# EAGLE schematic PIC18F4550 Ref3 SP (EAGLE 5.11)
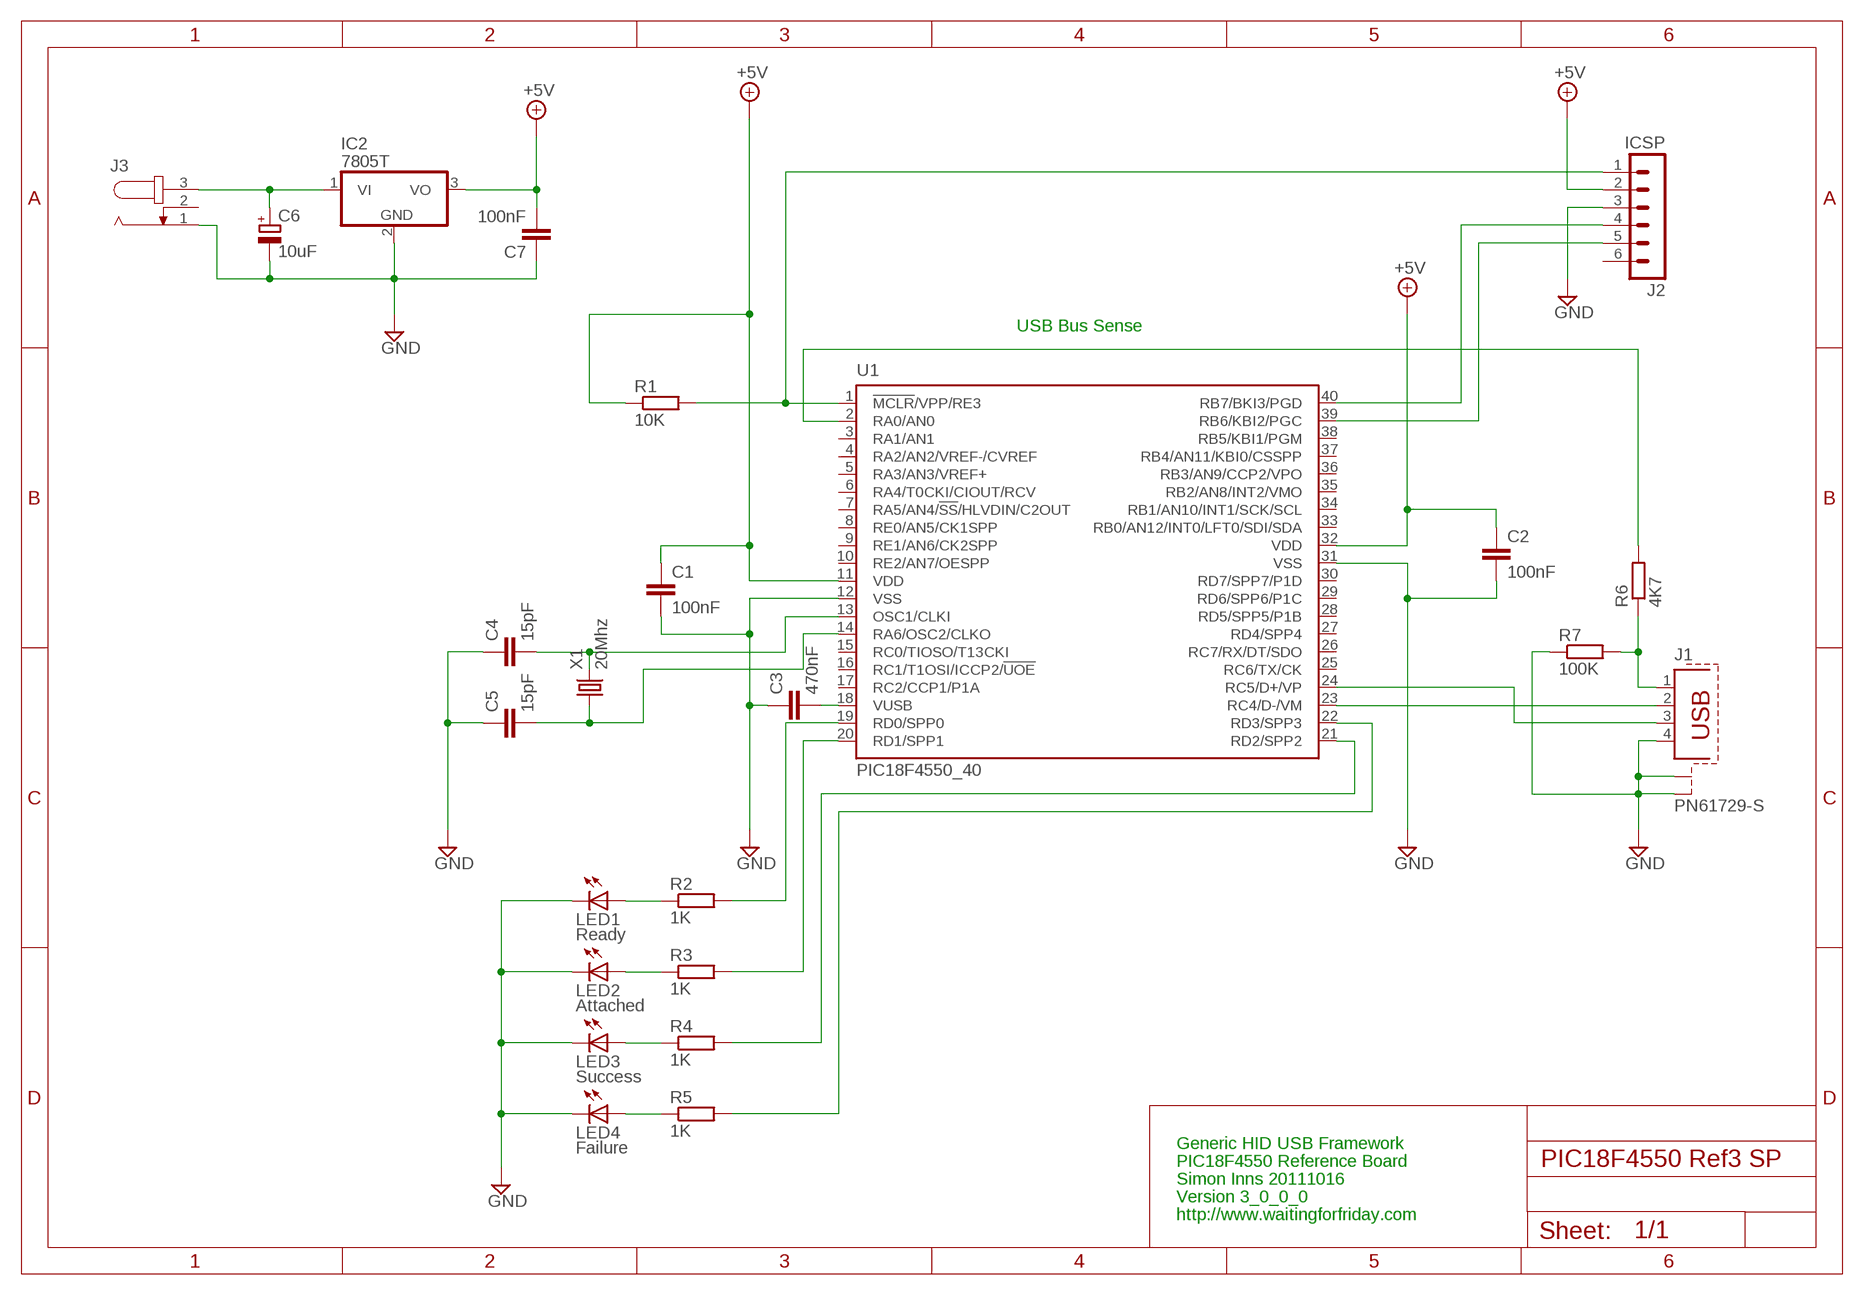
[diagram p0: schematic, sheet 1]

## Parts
C1  100nF  C-EU075-032X103  [C075-032X103]
C2  100nF  C-EU075-032X103  [C075-032X103]
C3  470nF  C-EU050-045X075  [C050-045X075]
C4  15pF  C-EU050-024X044  [C050-024X044]
C5  15pF  C-EU050-024X044  [C050-024X044]
C6  10uF  CPOL-EUE2.5-5  [E2,5-5]
C7  100nF  C-EU075-032X103  [C075-032X103]
IC2  7805T  [TO220H]
J1  PN61729-S  [PN61729-S]
J2  ICSP  MA06-1  [MA06-1]
J3  JACK-PLUG0  [SPC4077]
LED1  Ready  LED3MM  [LED3MM]
LED2  Attached  LED3MM  [LED3MM]
LED3  Success  LED3MM  [LED3MM]
LED4  Failure  LED3MM  [LED3MM]
R1  10K  R-EU_0207/10  [0207/10]
R2  1K  R-EU_0207/10  [0207/10]
R3  1K  R-EU_0207/10  [0207/10]
R4  1K  R-EU_0207/10  [0207/10]
R5  1K  R-EU_0207/10  [0207/10]
R6  4K7  R-EU_0207/10  [0207/10]
R7  100K  R-EU_0207/10  [0207/10]
U1  PIC18F4550_40  [DIL40]
X1  20Mhz  CRYSTALHC49U-V  [HC49U-V]

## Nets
+5V: C1.1 C2.1 C7.2 IC2.3(VO) J2.2 R1.1 U1.11(VDD) U1.32(VDD)
GND: C1.2 C2.2 C3.1 C4.1 C5.1 C6.- C7.1 IC2.2(GND) J1.4 J1.S1 J1.S2 J2.3 J3.1 LED1.K(C) LED2.K(C) LED3.K(C) LED4.K(C) R7.1 U1.12(VSS) U1.31(VSS)
N$1: J2.1 R1.2 U1.1(!MCLR!/VPP/RE3)
N$2: LED1.A R2.1
N$3: LED2.A R3.1
N$4: LED3.A R4.1
N$5: LED4.A R5.1
N$6: C4.2 U1.13(OSC1/CLKI) X1.2
N$7: C5.2 U1.14(RA6/OSC2/CLKO) X1.1
N$8: R2.2 U1.19(RD0/SPP0)
N$9: J2.4 U1.40(RB7/BKI3/PGD)
N$10: J2.5 U1.39(RB6/KBI2/PGC)
N$11: C3.2 U1.18(VUSB)
N$12: J1.2 U1.23(RC4/D-/VM)
N$13: J1.3 U1.24(RC5/D+/VP)
N$14: R3.2 U1.20(RD1/SPP1)
N$15: R4.2 U1.21(RD2/SPP2)
N$16: R5.2 U1.22(RD3/SPP3)
N$17: C6.+ IC2.1(VI) J3.3
N$18: J1.1 R6.1 R7.2
N$20: R6.2 U1.2(RA0/AN0)
Unconnected: J2.6 J3.2 U1.3(RA1/AN1) U1.4(RA2/AN2/VREF-/CVREF) U1.5(RA3/AN3/VREF+) U1.6(RA4/T0CKI/CIOUT/RCV) U1.7(RA5/AN4/!SS!/HLVDIN/C2OUT) U1.8(RE0/AN5/CK1SPP) U1.9(RE1/AN6/CK2SPP) U1.10(RE2/AN7/OESPP) U1.15(RC0/TIOSO/T13CKI) U1.16(RC1/T1OSI/ICCP2/!UOE) U1.17(RC2/CCP1/P1A) U1.25(RC6/TX/CK) U1.26(RC7/RX/DT/SDO) U1.27(RD4/SPP4) U1.28(RD5/SPP5/P1B) U1.29(RD6/SPP6/P1C) U1.30(RD7/SPP7/P1D) U1.33(RB0/AN12/INT0/LFT0/SDI/SDA) U1.34(RB1/AN10/INT1/SCK/SCL) U1.35(RB2/AN8/INT2/VMO) U1.36(RB3/AN9/CCP2/VPO) U1.37(RB4/AN11/KBI0/CSSPP) U1.38(RB5/KBI1/PGM)

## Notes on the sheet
- USB Bus Sense
- Generic HID USB Framework
- PIC18F4550 Reference Board
- Simon Inns 20111016
- Version 3_0_0_0
- http://www.waitingforfriday.com

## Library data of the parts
C1-C5 C7 = rcl:C-EU: CAPACITOR, European symbol
C6 = rcl:CPOL-EU: POLARIZED CAPACITOR, European symbol
IC2 = linear:78*: Positive VOLTAGE REGULATOR Source: http://cache.national.com/ds/LM/LM78L05.pdf http://www.fairchildsemi.com/ds/LM/LM7805.pdf
J1 = con-berg:PN61729-S: BERG USB connector; OC_FARNELL: unknown; OC_NEWARK: unknown
J2 = con-lstb:MA06-1: PIN HEADER; OC_FARNELL: unknown; OC_NEWARK: unknown
J3 = con-jack:JACK-PLUG: DC POWER JACK Power Jack, DC, Right Angle, Through Hole, Rated 5A at 16VDC, PC Terminals Distributor: Farnell (www.Farnell.de) Drawing: 84N1161.pdf / 84N1162.pdf Manufacturer: SPC Technology (www.spctechnology.com) Type: SPC4077 / SPC 4078; OC_FARNELL: unknown; OC_NEWARK: unknown
LED1-LED4 = led:LED: LED
R1-R7 = rcl:R-EU_: RESISTOR, European symbol
U1 = microchip:PIC18F4*_40: USB Microcontrollers with nanoWatt Technology High-Performance, Enhanced Flash, 28/40/44-Pin, Source: http://ww1.microchip.com/downloads/en/devicedoc/39632c.pdf; MF: MICROCHIP; MPN: PIC18F4550-I/P; OC_FARNELL: 9321357; OC_NEWARK: 74K8623
X1 = crystal:CRYSTAL: CRYSTAL; OC_FARNELL: 1666969; OC_NEWARK: unknown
